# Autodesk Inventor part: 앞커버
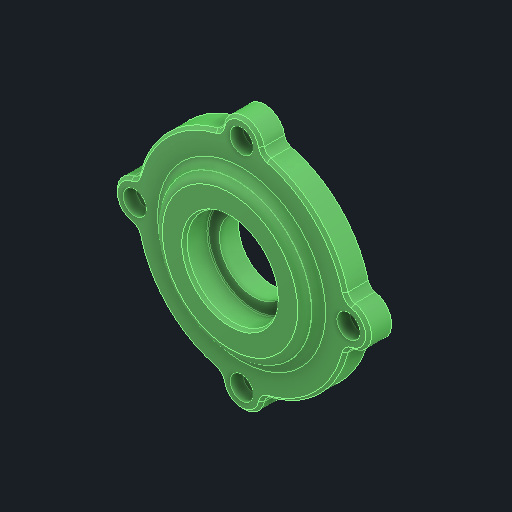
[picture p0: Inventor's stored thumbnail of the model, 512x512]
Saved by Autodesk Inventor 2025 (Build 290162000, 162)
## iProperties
Created: 2025-08
Part Number: 앞커버
Material: 알루미늄 6061
Document SubType Name: Modeling
Designer: infra14
Density: 2.71 g/cm^3
Appearance: 기본값
Company: 한국ATC센터
Author: jhkim
Sending System: Autodesk Inventor 2026
Preprocessor: ST-DEVELOPER v20.1
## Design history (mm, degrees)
feature "솔리드1"
node "솔리드2"
